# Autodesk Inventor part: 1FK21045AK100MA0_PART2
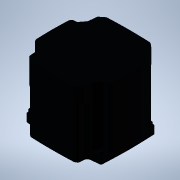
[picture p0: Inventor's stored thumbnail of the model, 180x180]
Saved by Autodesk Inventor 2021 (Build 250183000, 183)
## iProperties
Created: 2025-04
Part Number: 1FK21045AK100MA0_PART2
Material: Generic
Catalog Web Link: www.3dfindit.com
Description: -Servo synchronous motor
Document SubType Name: Modeling
Designer: psAdmin
Mass: 372.123 g
Surface Area: 313.117 cm^2
Volume: 372.123 cm^3
Density: 1 g/cm^3
Appearance: PSOLRGB-38-46-56
Category: PARTsolutions
Title: 1FK21045AK100MA0_PART2
Author: Cadenas PARTsolutions
Comments: Servo synchronous motor
Sending System: PARTsolutions
Preprocessor: ST-DEVELOPER v19.3
PSOL_IDENT_0: {$CADENAS_DATA/23d-libs/siemens_ag/_cat_/e0/5f/1fk21045ak100ma0.prj},213 {VTYP=3D},{NB=1FK21045AK100
PSOL_IDENT_1: MA0_PART2},{LINA=1FK21045AK100MA0_PART2},{NN=1FK21045AK100MA0_PART2},{NOPRJ=TRUE},{DATE=19.08.2025 1
PSOL_IDENT_2: 4:01:03},{GEOMDATE=30.07.2025 02:01:57},{VERSION=},{LINEID=10},{WBVAR=},{WBNUMERIC=}  {NB=1FK21045AK
PSOL_IDENT_3: 100MA0_PART2},{LINA=1FK21045AK100MA0_PART2},{KT=DUMMY},{PREVIEW=../../../_pool_/0f/2c/p_d211_xx_0043
PSOL_IDENT_4: 8j.png},{DESCSHORT=SIMOTICS S-1FK2 HD, SINAMICS S210 3AC 400V-480V, 1.7 Nm, 6000 rpm},{DESCLONG=SIMO
PSOL_IDENT_5: TICS S-1FK2 HD servo motor M0=2.4 Nm; PN = 1.07 kW at nN=6000 rpm (380-480 V); PN = 0.75 kW at nN=30
PSOL_IDENT_6: 00 rpm (200-240 V); with holding brake; degree of protection IP64; cylindrical shaft D19x40mm; absol
PSOL_IDENT_7: ute encoder 22-bit + 12-bit multiturn (encoder AM22DQC); with OCC interface; plug size M17, rotatabl
PSOL_IDENT_8: e; SIMOTICS S-1FK2 servomotorfor a wide range of uses in industrial environments. SIMOTICS S‑1FK2 se
PSOL_IDENT_9: rvomotors are compact synchronous motors with a high dynamic performance that set themselves apart a
PSOL_IDENT_10: s a result of their high power density, degree of protection and overload capability. The motors are
PSOL_IDENT_11: available in two variants: as High Dynamic variant (highest dynamic performance as a result of the
PSOL_IDENT_12: low intrinsic moment of inertia for applications demanding a high dynamic performance with low moved
PSOL_IDENT_13: masses) - and as Compact variant (precise and stable closed-loop control for medium up to large mov
PSOL_IDENT_14: ed masses as a result of a medium intrinsic moment of inertia). SIMOTICSS‑1FK2 servomotors fully exp
PSOL_IDENT_15: loit their strengths in a system with the SINAMICSS210 frequency converter and simple connection usi
PSOL_IDENT_16: ng the one cable connection (OCC). Advantages include the short control and positioning times, fast
PSOL_IDENT_17: and precise correction of disturbing quantities as well as stable control with a high dynamic perfor
PSOL_IDENT_18: mance. The servo motors can be configured to address a wide range of requirements. For example with
PSOL_IDENT_19: and without holding brake, IP64 or IP65 degree of protection, singleturn or multiturn absolute encod
PSOL_IDENT_20: ers - to name just a few. Further, the servomotors are available in different shaft heights extendin
PSOL_IDENT_21: g from 20 to 100. A shaft sealing ring is available to achieve an IP65 degree of protection and for
PSOL_IDENT_22: subsequent mounting at the motor or as spare part. SIMOTICS - the optimum motor for each and every m
PSOL_IDENT_23: otion control application.},{INTNO=804766807114},{SUPPLIERALTNO=1FK2104-5AK10-0MA0},{MANUID=1FK21045
PSOL_IDENT_24: AK100MA0},{MANUNAME=Siemens},{MANUTYPEDESC=Synchronous motor 1FK2-HD 2,39 Nm},{AAU732=SIMOTICS},{AAO
PSOL_IDENT_25: 057=S-1FK2},{AAU734=SIMOTICS S-1FK2 HD servo motor M0=2.4 Nm; PN = 1.07 kW at nN=6000 rpm (380-480 V
PSOL_IDENT_26: ); PN = 0.75 kW at nN=3000 rpm (200-240 V); with holding brake; degree of protection IP64; cylindric
PSOL_IDENT_27: al shaft D19x40mm; absolute encoder 22-bit + 12-bit multiturn (encoder AM22DQC); with OCC interface;
PSOL_IDENT_28: plug size M17, rotatable;},{AAW338=Synchronous motor 1FK2-HD 2,39 Nm},{AAO742=SIMOTICS},{AAO663=404
PSOL_IDENT_29: 2948691236},{NOCUPEROU=1},{PRICEQUANTITY=1},{QUANTITYMIN=1},{QUANTITYINT=1},{CTN=85015100},{COO=DE},
PSOL_IDENT_30: {AAO676=1FK2104-5AK10-0MA0},{AAO677=Siemens AG},{ORDERUNIT=C62},{CONTENTUNIT=C62}
NB: 1FK21045AK100MA0_PART2
NT: Servo synchronous motor
NBSYN: $MANUID._PART2
LINA: 1FK21045AK100MA0_PART2
CATALOG: SIEMENS
PREVIEW: ../../../_pool_/0f/2c/p_d211_xx_00438j.png
DESCSHORT: SIMOTICS S-1FK2 HD, SINAMICS S210 3AC 400V-480V, 1.7 Nm, 6000 rpm
DESCLONG: SIMOTICS S-1FK2 HD servo motor M0=2.4 Nm; PN = 1.07 kW at nN=6000 rpm (380-480 V); PN = 0.75 kW at nN=3000 rpm (200-240 V); with holding brake; degree of protec
INTNO: 804766807114
SUPPLIERALTNO: 1FK2104-5AK10-0MA0
MANUID: 1FK21045AK100MA0
MANUNAME: Siemens
MANUTYPEDESC: Synchronous motor 1FK2-HD 2,39 Nm
AAU732: SIMOTICS
AAO057: S-1FK2
AAU734: SIMOTICS S-1FK2 HD servo motor M0=2.4 Nm; PN = 1.07 kW at nN=6000 rpm (380-480 V); PN = 0.75 kW at nN=3000 rpm (200-240 V); with holding brake; degree of protec
AAW338: Synchronous motor 1FK2-HD 2,39 Nm
AAO742: SIMOTICS
AAO663: 4042948691236.0
NOCUPEROU: 1
PRICEQUANTITY: 1
QUANTITYMIN: 1
QUANTITYINT: 1
CTN: 85015100
COO: DE
ARTICLENO: 1FK21045AK100MA0_PART2
BOMINFO: 1FK21045AK100MA0_PART2
CREATOR: CADENAS GmbH
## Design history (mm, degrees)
feature "2025_04_17_15_45_15_0011"
body "Solid1"
